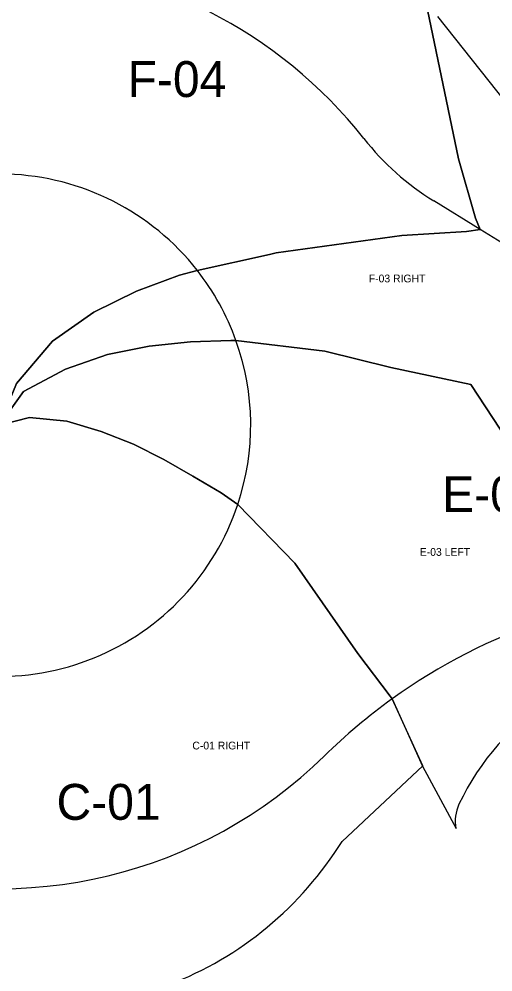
# Model space of a CAD drawing. Extents: x 5196716 to 5200291, y 3709146 to 3713154.
# Drawn here: x 5196904.7 to 5196983.8, y 3709265.9 to 3709425.2 of the extents above; entities that cross this region are included whole.
import ezdxf

# ---------------------------------------------------------------- set-up
doc = ezdxf.new("R2010")
doc.units = 0
for name, color, linetype in [('dsnTextNote', 7, 'Continuous'), ('Level 1', 7, 'Continuous'), ('Level 2', 7, 'Continuous'), ('Level 4', 7, 'Continuous')]:
    doc.layers.add(name, color=color, linetype=linetype)

msp = doc.modelspace()

# ---------------------------------------------------------------- linework, layer by layer
at = {"layer": 'Level 1'}
for p, q in [((5196993.25, 3709402.11), (5196974.62, 3709425.62)), ((5196933.29, 3709371.24), (5196926.43, 3709370.49)), ((5196926.43, 3709370.49), (5196933.29, 3709371.24)), ((5196940.04, 3709371.46), (5196933.29, 3709371.24)), ((5196933.29, 3709371.24), (5196940.04, 3709371.46)), ((5196940.9, 3709371.45), (5196940.04, 3709371.46)), ((5196940.04, 3709371.46), (5196940.9, 3709371.45)), ((5196955.72, 3709369.66), (5196940.9, 3709371.45)), ((5196940.9, 3709371.45), (5196955.72, 3709369.66)), ((5196926.43, 3709370.49), (5196919.45, 3709369.09)), ((5196919.45, 3709369.09), (5196926.43, 3709370.49)), ((5196966.78, 3709366.95), (5196955.72, 3709369.66)), ((5196955.72, 3709369.66), (5196966.78, 3709366.95)), ((5196919.45, 3709369.09), (5196912.45, 3709366.66)), ((5196912.45, 3709366.66), (5196919.45, 3709369.09)), ((5196912.45, 3709366.66), (5196905.44, 3709362.91)), ((5196905.44, 3709362.91), (5196912.45, 3709366.66)), ((5196980.1, 3709364.11), (5196966.78, 3709366.95)), ((5196966.78, 3709366.95), (5196980.1, 3709364.11)), ((5196987.74, 3709352.43), (5196980.1, 3709364.11)), ((5196980.1, 3709364.11), (5196987.74, 3709352.43)), ((5196905.44, 3709362.91), (5196901.36, 3709357.29)), ((5196901.36, 3709357.29), (5196905.44, 3709362.91)), ((5196901.36, 3709357.29), (5196906.42, 3709358.57)), ((5196906.42, 3709358.57), (5196901.36, 3709357.29)), ((5196906.42, 3709358.57), (5196912.67, 3709357.94)), ((5196912.67, 3709357.94), (5196906.42, 3709358.57)), ((5196912.67, 3709357.94), (5196918.38, 3709356.24)), ((5196918.38, 3709356.24), (5196912.67, 3709357.94)), ((5196918.38, 3709356.24), (5196923.78, 3709354.11)), ((5196923.78, 3709354.11), (5196918.38, 3709356.24)), ((5196923.78, 3709354.11), (5196928.83, 3709351.55)), ((5196928.83, 3709351.55), (5196923.78, 3709354.11)), ((5196928.83, 3709351.55), (5196933.68, 3709348.76)), ((5196933.68, 3709348.76), (5196928.83, 3709351.55)), ((5196933.68, 3709348.76), (5196938.45, 3709346.01)), ((5196938.45, 3709346.01), (5196933.68, 3709348.76)), ((5196938.45, 3709346.01), (5196941.21, 3709344.04)), ((5196941.21, 3709344.04), (5196938.45, 3709346.01)), ((5196941.21, 3709344.04), (5196950.73, 3709334.21)), ((5196950.73, 3709334.21), (5196941.21, 3709344.04)), ((5196950.73, 3709334.21), (5196961.24, 3709319.1)), ((5196961.24, 3709319.1), (5196966.66, 3709311.97)), ((5196966.66, 3709311.97), (5196966.99, 3709311.54))]:
    msp.add_line(p, q, dxfattribs=at)
for points in [[(5196972.61, 3709428.08), (5196978.06, 3709401.82), (5196980.89, 3709391.88), (5196981.68, 3709390)], [(5196981.68, 3709390), (5196980.89, 3709391.88), (5196978.06, 3709401.82), (5196972.61, 3709428.08)], [(5196981.68, 3709390), (5196979.42, 3709389.66), (5196968.63, 3709389), (5196947.61, 3709386.12)], [(5196947.61, 3709386.12), (5196968.63, 3709389), (5196979.42, 3709389.66), (5196981.68, 3709390)], [(5196947.61, 3709386.12), (5196946.48, 3709385.84), (5196934.43, 3709383.18)], [(5196934.43, 3709383.18), (5196946.48, 3709385.84), (5196947.61, 3709386.12)], [(5196934.43, 3709383.18), (5196931.47, 3709382.38), (5196924.29, 3709379.72), (5196917.18, 3709376.21), (5196910.26, 3709371.32), (5196904.27, 3709364.25), (5196901.36, 3709357.29)], [(5196901.36, 3709357.29), (5196904.27, 3709364.25), (5196910.26, 3709371.32), (5196917.18, 3709376.21), (5196924.29, 3709379.72), (5196931.47, 3709382.38), (5196934.43, 3709383.18)], [(5196966.99, 3709311.54), (5196966.66, 3709311.97), (5196961.24, 3709319.1), (5196950.73, 3709334.21)], [(5196958.63, 3709287.71), (5196972.11, 3709300.33), (5196966.99, 3709311.54)], [(5196966.99, 3709311.54), (5196972.07, 3709300.27), (5196977.65, 3709289.84)]]:
    msp.add_lwpolyline(points, dxfattribs=at)
for centre, radius, start, end in [((5197016.01, 3709276.13), 41.83, 89.8345, 154.8409), ((5196984.13, 3709291.1), 6.61, 154.8409, 191.0282), ((5196908.25, 3709319.03), 59.32, 291.2079, 328.1296)]:
    msp.add_arc(centre, radius, start, end, dxfattribs=at)
at = {"layer": 'Level 2'}
for p, q in [((5196981.68, 3709390), (5196973.96, 3709394.78)), ((5196981.68, 3709390), (5196979.42, 3709389.66)), ((5196996.1, 3709381.08), (5196981.68, 3709390)), ((5196940.9, 3709371.45), (5196955.72, 3709369.66)), ((5196955.72, 3709369.66), (5196940.9, 3709371.45)), ((5196955.72, 3709369.66), (5196966.78, 3709366.95)), ((5196966.78, 3709366.95), (5196955.72, 3709369.66)), ((5196966.78, 3709366.95), (5196980.1, 3709364.11)), ((5196980.1, 3709364.11), (5196966.78, 3709366.95)), ((5196980.1, 3709364.11), (5196987.74, 3709352.43)), ((5196987.74, 3709352.43), (5196980.1, 3709364.11)), ((5196950.73, 3709334.21), (5196941.21, 3709344.04)), ((5196941.21, 3709344.04), (5196950.73, 3709334.21)), ((5196961.24, 3709319.1), (5196950.73, 3709334.21)), ((5196966.66, 3709311.97), (5196961.24, 3709319.1)), ((5196966.99, 3709311.54), (5196966.66, 3709311.97)), ((5196966.66, 3709311.97), (5196966.99, 3709311.54))]:
    msp.add_line(p, q, dxfattribs=at)
for points in [[(5196947.61, 3709386.12), (5196968.63, 3709389), (5196979.42, 3709389.66), (5196981.68, 3709390)], [(5196979.42, 3709389.66), (5196968.63, 3709389), (5196947.61, 3709386.12)], [(5196934.43, 3709383.18), (5196946.48, 3709385.84), (5196947.61, 3709386.12)], [(5196947.61, 3709386.12), (5196946.48, 3709385.84), (5196934.43, 3709383.18)], [(5196950.73, 3709334.21), (5196961.24, 3709319.1), (5196966.66, 3709311.97)]]:
    msp.add_lwpolyline(points, dxfattribs=at)
for centre, radius, start, end in [((5196901.36, 3709357.29), 77.5, 38.2026, 88.1128), ((5196997.62, 3709433.05), 45, 218.2026, 238.2692), ((5196901.36, 3709357.29), 42, 38.0641, 88.1128), ((5196901.36, 3709357.29), 42, 19.7106, 38.0641), ((5196901.36, 3709357.29), 42, 341.6137, 19.7106), ((5196901.36, 3709357.29), 42, 242.7935, 341.6137), ((5197023.98, 3709232.43), 97.5, 91.6298, 125.7719), ((5197023.98, 3709232.43), 97.5, 125.7719, 134.4832), ((5196901.36, 3709357.29), 77.5, 252.6379, 314.4832)]:
    msp.add_arc(centre, radius, start, end, dxfattribs=at)
at = {"layer": 'Level 4'}
for p, q in [((5196931.47, 3709382.38), (5196924.29, 3709379.72)), ((5196934.43, 3709383.18), (5196931.47, 3709382.38)), ((5196933.29, 3709371.24), (5196926.43, 3709370.49)), ((5196926.43, 3709370.49), (5196933.29, 3709371.24)), ((5196940.04, 3709371.46), (5196933.29, 3709371.24)), ((5196933.29, 3709371.24), (5196940.04, 3709371.46)), ((5196940.9, 3709371.45), (5196940.04, 3709371.46)), ((5196940.04, 3709371.46), (5196940.9, 3709371.45)), ((5196926.43, 3709370.49), (5196919.45, 3709369.09)), ((5196919.45, 3709369.09), (5196926.43, 3709370.49)), ((5196919.45, 3709369.09), (5196912.45, 3709366.66)), ((5196912.45, 3709366.66), (5196919.45, 3709369.09)), ((5196912.45, 3709366.66), (5196905.44, 3709362.91)), ((5196905.44, 3709362.91), (5196912.45, 3709366.66)), ((5196905.44, 3709362.91), (5196901.36, 3709357.29)), ((5196901.36, 3709357.29), (5196905.44, 3709362.91)), ((5196906.42, 3709358.57), (5196901.36, 3709357.29)), ((5196901.36, 3709357.29), (5196906.42, 3709358.57)), ((5196912.67, 3709357.94), (5196906.42, 3709358.57)), ((5196906.42, 3709358.57), (5196912.67, 3709357.94)), ((5196918.38, 3709356.24), (5196912.67, 3709357.94)), ((5196912.67, 3709357.94), (5196918.38, 3709356.24)), ((5196923.78, 3709354.11), (5196918.38, 3709356.24)), ((5196918.38, 3709356.24), (5196923.78, 3709354.11)), ((5196928.83, 3709351.55), (5196923.78, 3709354.11)), ((5196923.78, 3709354.11), (5196928.83, 3709351.55)), ((5196933.68, 3709348.76), (5196928.83, 3709351.55)), ((5196928.83, 3709351.55), (5196933.68, 3709348.76)), ((5196938.45, 3709346.01), (5196933.68, 3709348.76)), ((5196933.68, 3709348.76), (5196938.45, 3709346.01)), ((5196941.21, 3709344.04), (5196938.45, 3709346.01)), ((5196938.45, 3709346.01), (5196941.21, 3709344.04))]:
    msp.add_line(p, q, dxfattribs=at)
for points in [[(5196901.36, 3709357.29), (5196904.27, 3709364.25), (5196910.26, 3709371.32), (5196917.18, 3709376.21), (5196924.29, 3709379.72), (5196931.47, 3709382.38), (5196934.43, 3709383.18)], [(5196924.29, 3709379.72), (5196917.18, 3709376.21), (5196910.26, 3709371.32), (5196904.27, 3709364.25), (5196901.36, 3709357.29)]]:
    msp.add_lwpolyline(points, dxfattribs=at)
for start, end in [(38.0641, 88.1128), (19.7106, 38.0641), (341.6137, 19.7106), (242.7935, 341.6137)]:
    msp.add_arc((5196901.36, 3709357.29), 42, start, end, dxfattribs=at)

# ---------------------------------------------------------------- texts
at = {"layer": 'dsnTextNote'}
for s, height, p in [('F-04', 6, (5196922.8, 3709412.16)), ('F-03 RIGHT', 1.3, (5196963.08, 3709381.17)), ('E-03', 6, (5196975.34, 3709342.76)), ('E-03 LEFT', 1.3, (5196971.6, 3709335.45)), ('C-01 RIGHT', 1.3, (5196933.61, 3709303.08)), ('C-01', 6, (5196910.93, 3709291.31))]:
    msp.add_text(s, height=height, dxfattribs=at).set_placement(p)

doc.saveas('drawing.dxf')
